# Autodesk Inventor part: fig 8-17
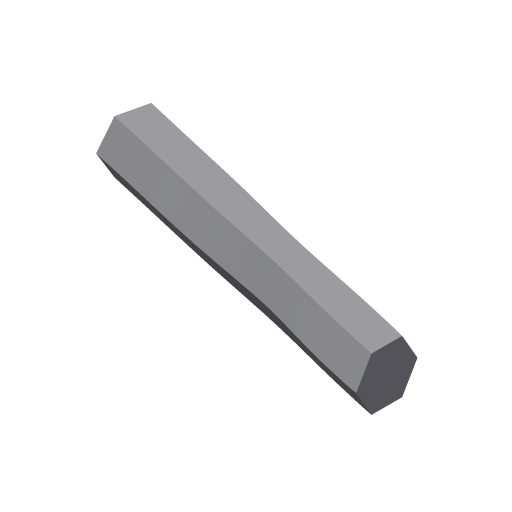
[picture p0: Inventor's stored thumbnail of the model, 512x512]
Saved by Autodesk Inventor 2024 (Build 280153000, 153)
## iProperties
Created: 2004-05
Part Number: fig 8-17
Document SubType Name: Modeling
Designer: CADCIM Technologies
Manufacturer: Standard
Standards Organization: Custom
Density: 1 g/cm^3
Material: Generic
Appearance: Default
Author: CADCIM Technologies
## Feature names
1. Sweep7
## Parameters: d6 = 0, d7 = 0
